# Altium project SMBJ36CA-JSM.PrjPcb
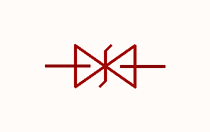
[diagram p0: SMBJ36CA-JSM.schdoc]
1 sheet, 1 parts. Net scope: global (net labels, ports and power ports of the same name join across sheets).

## Sheet SMBJ36CA-JSM.schdoc
size 127 x 101 mm

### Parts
D?  smbj36ca-jsm  [SMB_L4.3-W3.6-LS5.4-BI]  (value not drawn)

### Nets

Not connected (* = marked no-connect by the designer): D? 1 2

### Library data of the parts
D? = smbj36ca-jsm: 极性:双向;反向截止电压(Vrwm):36V;钳位电压:58.1V;峰值脉冲电流(Ipp):10.4A;峰值脉冲功率(Ppp):600W;击穿电压(VBR):44.2V;; Manufacturer: JSMSEMI(杰盛微); AddInBom: yes; ModelId: c0b8639b880e4a4bb7f1ec731307fbc2; ModelTransform: 212.598,142.5194,0,0,0,0,0,0,0; Polarity: 双向; Reverse Stand-Off Voltage (Vrwm): 36V; Clamping Voltage: 58.1V; Peak Pulse Current (Ipp): 10.4A; Peak Pulse Power Dissipation (Ppp): 600W; Voltage - Breakdown: 44.2V; Reverse Leakage Current (Ir): 1uA; Number of Channels: 单路; Type: TVS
